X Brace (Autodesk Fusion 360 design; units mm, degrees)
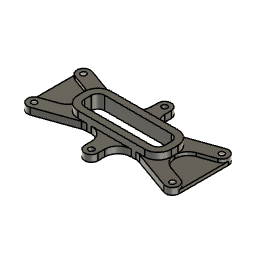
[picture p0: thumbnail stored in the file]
sketch "Sketch1" plane through (0, 0, 0) normal (0, 0, 1) x axis (1, 0, 0)
  line L1 (-44.45, -15.875) -> (44.45, -15.875)
  line L2 (-44.45, 15.875) -> (-44.45, -15.875)
  line L3 (44.45, 15.875) -> (-44.45, 15.875)
  line L4 (44.45, -15.875) -> (44.45, 15.875)
  line L5 (-44.45, 15.875) -> (44.45, -15.875)
  line L6 (44.45, 15.875) -> (-44.45, -15.875)
  line L7 (-63.6449, 29.4732) -> (67.9164, -17.513)
  line L8 (63.6449, -29.4732) -> (-67.9164, 17.513)
  line L9 (-65.7807, 23.4931) -> (65.7807, -23.4931)
  line L10 (67.9164, 17.513) -> (-63.6449, -29.4732)
  line L11 (-67.9164, -17.513) -> (63.6449, 29.4732)
  line L12 (65.7807, 23.4931) -> (-65.7807, -23.4931)
  line L13 (-72.1307, -23.4931) -> (-72.1307, 23.4931)
  line L14 (72.1307, -23.4931) -> (72.1307, 23.4931)
  arc A1 centre (-65.7807, 23.4931) radius 6.35 clockwise from (-67.9164, 17.513) to (-63.6449, 29.4732)
  arc A2 centre (65.7807, -23.4931) radius 6.35 clockwise from (67.9164, -17.513) to (63.6449, -29.4732)
  arc A3 centre (65.7807, 23.4931) radius 6.35 clockwise from (63.6449, 29.4732) to (67.9164, 17.513)
  arc A4 centre (-65.7807, -23.4931) radius 6.35 clockwise from (-63.6449, -29.4732) to (-67.9164, -17.513)
  point P6 (0, 0)
  point P1 (0, 0)
  point P13 (0, 0)
  point P20 (0, 0)
  point P21 (-72.1307, 23.4931)
  point P22 (-72.1307, -23.4931)
  point P23 (72.1307, 23.4931)
  point P24 (72.1307, -23.4931)
  point P4 (-44.45, 15.875)
  point P5 (44.45, 15.875)
  point P3 (-44.45, -15.875)
  point P11 (65.7807, -23.4931)
  point P12 (-65.7807, 23.4931)
  perpendicular L1 L2
  parallel L1 L3
  parallel L2 L4
  horizontal L1
  coincident L5 P6
  coincident L6 P6
  coincident P1 P6
  tangent L7 A1
  tangent A1 L8
  parallel L7 L8
  tangent L8 A2
  tangent L7 A2
  parallel L5 L9
  coincident L5 P13
  midpoint L9 P13
  coincident P1 P13
  tangent L10 A3
  tangent A3 L11
  parallel L10 L11
  tangent L11 A4
  tangent L10 A4
  parallel L6 L12
  coincident P13 P20
  midpoint L12 P20
  equal A2 A3
  equal L9 L12
  coincident A1 P21
  coincident A4 P22
  tangent A4 L13
  vertical L13
  coincident A3 P23
  coincident A2 P24
  tangent A2 L14
  vertical L14
  dimension "d1" distance P4 P5 = 88.9
  dimension "d2" distance P3 P4 = 31.75
  dimension "d3" radius A2 = 6.35
  dimension "d4" distance P11 P12 = 139.7
extrude "Extrude1" new body sketch "Sketch1" profile of L1 L2 L3 L4 L7 A1 L8 A2 L10 A3 L11 A4 along normal blind 6.35
extrude "Extrude2" add sketch "Sketch1" profile of L1 L2 L3 L4 L7 L8 L10 L11 along normal blind 12.7
fillet "Fillet1" radius 12.7
fillet "Fillet2" radius 12.7
sketch "Sketch2" plane through (0, 0, 12.7) normal (0, 0, 1) x axis (-1, 0, 0)
  line L1 (-31.75, 15.875) -> (31.75, 15.875)
  line L2 (-44.45, -3.175) -> (-44.45, 3.175)
  line L3 (31.75, -15.875) -> (-31.75, -15.875)
  line L4 (44.45, 3.175) -> (44.45, -3.175)
  line L5 (38.1, 3.175) -> (38.1, -3.175)
  line L6 (-31.75, 9.525) -> (31.75, 9.525)
  line L7 (-38.1, -3.175) -> (-38.1, 3.175)
  line L8 (31.75, -9.525) -> (-31.75, -9.525)
  arc A1 centre (31.75, 3.175) radius 12.7 clockwise from (31.75, 15.875) to (44.45, 3.175)
  arc A2 centre (-31.75, 3.175) radius 12.7 clockwise from (-44.45, 3.175) to (-31.75, 15.875)
  arc A3 centre (-31.75, -3.175) radius 12.7 clockwise from (-31.75, -15.875) to (-44.45, -3.175)
  arc A4 centre (31.75, -3.175) radius 12.7 clockwise from (44.45, -3.175) to (31.75, -15.875)
  arc A5 centre (31.75, 3.175) radius 6.35 clockwise from (31.75, 9.525) to (38.1, 3.175)
  arc A6 centre (-31.75, 3.175) radius 6.35 clockwise from (-38.1, 3.175) to (-31.75, 9.525)
  arc A7 centre (-31.75, -3.175) radius 6.35 clockwise from (-31.75, -9.525) to (-38.1, -3.175)
  arc A8 centre (31.75, -3.175) radius 6.35 clockwise from (38.1, -3.175) to (31.75, -9.525)
  dimension "d11" distance L4 = -6.35
extrude "Extrude3" cut sketch "Sketch2" profile of L5 A7 A5 L6 A6 L7 A8 L8 no distance stored
sketch "Sketch3" plane through (0, 0, 0) normal (0, 0, -1) x axis (1, 0, 0)
  line L1 (38.1, -3.175) -> (38.1, 3.175)
  line L2 (-31.75, -9.525) -> (31.75, -9.525)
  line L3 (-38.1, 3.175) -> (-38.1, -3.175)
  line L4 (31.75, 9.525) -> (-31.75, 9.525)
  line L5 (-44.45, -0.1822) -> (-44.45, 0.1822)
  line L6 (-67.9164, -17.513) -> (-52.8785, -12.1424)
  line L7 (-27.6418, -16.6149) -> (-63.6449, -29.4732)
  line L8 (23.3703, -15.875) -> (-23.3703, -15.875)
  line L9 (63.6449, -29.4732) -> (27.6418, -16.6149)
  line L10 (52.8785, -12.1424) -> (67.9164, -17.513)
  line L11 (44.45, 0.1822) -> (44.45, -0.1822)
  line L12 (67.9164, 17.513) -> (52.8785, 12.1424)
  line L13 (27.6418, 16.6149) -> (63.6449, 29.4732)
  line L14 (-23.3703, 15.875) -> (23.3703, 15.875)
  line L15 (-63.6449, 29.4732) -> (-27.6418, 16.6149)
  line L16 (-52.8785, 12.1424) -> (-67.9164, 17.513)
  arc A1 centre (31.75, -3.175) radius 6.35 clockwise from (38.1, -3.175) to (31.75, -9.525)
  arc A2 centre (-31.75, -3.175) radius 6.35 clockwise from (-31.75, -9.525) to (-38.1, -3.175)
  arc A3 centre (-31.75, 3.175) radius 6.35 clockwise from (-38.1, 3.175) to (-31.75, 9.525)
  arc A4 centre (31.75, 3.175) radius 6.35 clockwise from (31.75, 9.525) to (38.1, 3.175)
  arc A5 centre (-57.15, 0.1822) radius 12.7 clockwise from (-52.8785, 12.1424) to (-44.45, 0.1822)
  arc A6 centre (-57.15, -0.1822) radius 12.7 clockwise from (-44.45, -0.1822) to (-52.8785, -12.1424)
  arc A7 centre (-65.7807, -23.4931) radius 6.35 clockwise from (-63.6449, -29.4732) to (-67.9164, -17.513)
  arc A8 centre (-23.3703, -28.575) radius 12.7 clockwise from (-27.6418, -16.6149) to (-23.3703, -15.875)
  arc A9 centre (23.3703, -28.575) radius 12.7 clockwise from (23.3703, -15.875) to (27.6418, -16.6149)
  arc A10 centre (65.7807, -23.4931) radius 6.35 clockwise from (67.9164, -17.513) to (63.6449, -29.4732)
  arc A11 centre (57.15, -0.1822) radius 12.7 clockwise from (52.8785, -12.1424) to (44.45, -0.1822)
  arc A12 centre (57.15, 0.1822) radius 12.7 clockwise from (44.45, 0.1822) to (52.8785, 12.1424)
  arc A13 centre (65.7807, 23.4931) radius 6.35 clockwise from (63.6449, 29.4732) to (67.9164, 17.513)
  arc A14 centre (23.3703, 28.575) radius 12.7 clockwise from (27.6418, 16.6149) to (23.3703, 15.875)
  arc A15 centre (-23.3703, 28.575) radius 12.7 clockwise from (-23.3703, 15.875) to (-27.6418, 16.6149)
  arc A16 centre (-65.7807, 23.4931) radius 6.35 clockwise from (-67.9164, 17.513) to (-63.6449, 29.4732)
  point P52 (-65.7807, 23.4931)
  point P53 (-65.7807, 23.4931)
  point P23 (-65.7807, -23.4931)
  point P54 (-65.7807, -23.4931)
  point P42 (65.7807, 23.4931)
  point P55 (65.7807, 23.4931)
  point P33 (65.7807, -23.4931)
  point P56 (65.7807, -23.4931)
  coincident P52 P53
  coincident P23 P54
  coincident P42 P55
  coincident P33 P56
hole "Hole1" HoleDepth 9.525 HoleDiameter 5.1054 TipAngle 118
sketch "Sketch4" plane through (0, 0, 0) normal (0, 0, -1) x axis (1, 0, 0)
  line L1 (38.1, -3.175) -> (38.1, 3.175)
  line L2 (-31.75, -9.525) -> (31.75, -9.525)
  line L3 (-38.1, 3.175) -> (-38.1, -3.175)
  line L4 (31.75, 9.525) -> (-31.75, 9.525)
  line L5 (-44.45, -0.1822) -> (-44.45, 0.1822)
  line L6 (-67.9164, -17.513) -> (-52.8785, -12.1424)
  line L7 (-27.6418, -16.6149) -> (-63.6449, -29.4732)
  line L8 (23.3703, -15.875) -> (-23.3703, -15.875)
  line L9 (63.6449, -29.4732) -> (27.6418, -16.6149)
  line L10 (52.8785, -12.1424) -> (67.9164, -17.513)
  line L11 (44.45, 0.1822) -> (44.45, -0.1822)
  line L12 (67.9164, 17.513) -> (52.8785, 12.1424)
  line L13 (27.6418, 16.6149) -> (63.6449, 29.4732)
  line L14 (-23.3703, 15.875) -> (23.3703, 15.875)
  line L15 (-63.6449, 29.4732) -> (-27.6418, 16.6149)
  line L16 (-52.8785, 12.1424) -> (-67.9164, 17.513)
  line L17 (-56.126, 26.7878) -> (-60.3975, 14.8277)
  line L18 (6.35, 15.875) -> (-6.35, 15.875)
  line L19 (6.35, 34.925) -> (6.35, 15.875)
  line L20 (-6.35, 34.925) -> (6.35, 34.925)
  line L21 (-6.35, 15.875) -> (-6.35, 34.925)
  line L22 (6.35, -15.875) -> (-6.35, -15.875)
  line L23 (6.35, -34.925) -> (6.35, -15.875)
  line L24 (-6.35, -34.925) -> (6.35, -34.925)
  line L25 (-6.35, -15.875) -> (-6.35, -34.925)
  line L26 (0, -15.875) -> (0, 15.875)
  circle C1 centre (65.7807, 23.4931) radius 2.5578
  circle C2 centre (-65.7807, 23.4931) radius 2.5578
  circle C3 centre (-65.7807, -23.4931) radius 2.5578
  circle C4 centre (65.7807, -23.4931) radius 2.5578
  arc A1 centre (31.75, -3.175) radius 6.35 clockwise from (38.1, -3.175) to (31.75, -9.525)
  arc A2 centre (-31.75, -3.175) radius 6.35 clockwise from (-31.75, -9.525) to (-38.1, -3.175)
  arc A3 centre (-31.75, 3.175) radius 6.35 clockwise from (-38.1, 3.175) to (-31.75, 9.525)
  arc A4 centre (31.75, 3.175) radius 6.35 clockwise from (31.75, 9.525) to (38.1, 3.175)
  arc A5 centre (-57.15, 0.1822) radius 12.7 clockwise from (-52.8785, 12.1424) to (-44.45, 0.1822)
  arc A6 centre (-57.15, -0.1822) radius 12.7 clockwise from (-44.45, -0.1822) to (-52.8785, -12.1424)
  arc A7 centre (-65.7807, -23.4931) radius 6.35 clockwise from (-63.6449, -29.4732) to (-67.9164, -17.513)
  arc A8 centre (-23.3703, -28.575) radius 12.7 clockwise from (-27.6418, -16.6149) to (-23.3703, -15.875)
  arc A9 centre (23.3703, -28.575) radius 12.7 clockwise from (23.3703, -15.875) to (27.6418, -16.6149)
  arc A10 centre (65.7807, -23.4931) radius 6.35 clockwise from (67.9164, -17.513) to (63.6449, -29.4732)
  arc A11 centre (57.15, -0.1822) radius 12.7 clockwise from (52.8785, -12.1424) to (44.45, -0.1822)
  arc A12 centre (57.15, 0.1822) radius 12.7 clockwise from (44.45, 0.1822) to (52.8785, 12.1424)
  arc A13 centre (65.7807, 23.4931) radius 6.35 clockwise from (63.6449, 29.4732) to (67.9164, 17.513)
  arc A14 centre (23.3703, 28.575) radius 12.7 clockwise from (27.6418, 16.6149) to (23.3703, 15.875)
  arc A15 centre (-23.3703, 28.575) radius 12.7 clockwise from (-23.3703, 15.875) to (-27.6418, 16.6149)
  arc A16 centre (-65.7807, 23.4931) radius 6.35 clockwise from (-67.9164, 17.513) to (-63.6449, 29.4732)
  circle C5 centre (0, 34.925) radius 6.35
  circle C6 centre (0, -34.925) radius 6.35
  circle C7 centre (0, -34.925) radius 2.5578
  circle C8 centre (0, 34.925) radius 2.5578
  point P51 (-56.126, 26.7878)
  point P50 (-60.3975, 14.8277)
  point P52 (-6.35, 15.875)
  point P56 (-6.35, -15.875)
  point P60 (0, 15.875)
  point P61 (0, -15.875)
  point P1 (0, 0)
  point P62 (0, 34.925)
  point P54 (6.35, 34.925)
  point P63 (0, -34.925)
  point P58 (6.35, -34.925)
  point P55 (-6.35, 34.925)
  coincident L15 P51
  perpendicular L15 L17
  midpoint L16 P50
  horizontal L18
  vertical L19
  horizontal L20
  vertical L21
  coincident L14 P52
  horizontal L22
  vertical L23
  horizontal L24
  vertical L25
  coincident L8 P56
  equal L17 L20
  equal L17 L24
  midpoint L18 P60
  midpoint L22 P61
  vertical L26
  midpoint P1 L26
  equal L19 L23
  midpoint L20 P62
  coincident P54 C5
  midpoint L24 P63
  coincident P58 C6
  concentric C6 C7
  concentric C5 C8
  equal C2 C8
  equal C7 C8
  dimension "d16" distance P52 P55 = 19.05
extrude "Extrude4" add sketch "Sketch4" profile of L8 L14 L18 L19 L20 L21 L22 L23 L24 L25 C5 C6 C7 C8 to an object
fillet "Fillet3" radius 12.7
extrude "Extrude5" add sketch "Sketch1" profile of L2 L4 L7 A1 L8 A2 L10 A3 L11 A4 L13 L14 along normal blind 3.175
sketch "Sketch5" plane through (0, 0, 0) normal (0, 0, -1) x axis (1, 0, 0)
  line L1 (38.1, -3.175) -> (38.1, 3.175)
  line L2 (-31.75, -9.525) -> (31.75, -9.525)
  line L3 (-38.1, 3.175) -> (-38.1, -3.175)
  line L4 (31.75, 9.525) -> (-31.75, 9.525)
  line L5 (72.1307, 23.4931) -> (72.1307, -23.4931)
  line L6 (27.6418, 16.6149) -> (63.6449, 29.4732)
  line L7 (19.05, 15.875) -> (23.3703, 15.875)
  line L8 (6.35, 34.925) -> (6.35, 28.575)
  line L9 (-6.35, 28.575) -> (-6.35, 34.925)
  line L10 (-23.3703, 15.875) -> (-19.05, 15.875)
  line L11 (-63.6449, 29.4732) -> (-27.6418, 16.6149)
  line L12 (-72.1307, -23.4931) -> (-72.1307, 23.4931)
  line L13 (-27.6418, -16.6149) -> (-63.6449, -29.4732)
  line L14 (-19.05, -15.875) -> (-23.3703, -15.875)
  line L15 (-6.35, -34.925) -> (-6.35, -28.575)
  line L16 (6.35, -28.575) -> (6.35, -34.925)
  line L17 (23.3703, -15.875) -> (19.05, -15.875)
  line L18 (63.6449, -29.4732) -> (27.6418, -16.6149)
  line L19 (-52.8785, -12.1424) -> (-67.9164, -17.513)
  line L20 (-44.45, -3.175) -> (-44.45, -0.1822)
  line L21 (-23.3703, -15.875) -> (-31.75, -15.875)
  line L22 (-63.6449, -29.4732) -> (-27.6418, -16.6149)
  line L23 (-31.75, 15.875) -> (-23.3703, 15.875)
  line L24 (-44.45, 0.1822) -> (-44.45, 3.175)
  line L25 (-67.9164, 17.513) -> (-52.8785, 12.1424)
  line L26 (-27.6418, 16.6149) -> (-63.6449, 29.4732)
  line L27 (67.9164, -17.513) -> (52.8785, -12.1424)
  line L28 (27.6418, -16.6149) -> (63.6449, -29.4732)
  line L29 (31.75, -15.875) -> (23.3703, -15.875)
  line L30 (44.45, -0.1822) -> (44.45, -3.175)
  line L31 (23.3703, 15.875) -> (31.75, 15.875)
  line L32 (63.6449, 29.4732) -> (27.6418, 16.6149)
  line L33 (52.8785, 12.1424) -> (67.9164, 17.513)
  line L34 (44.45, 3.175) -> (44.45, 0.1822)
  line L35 (-30.7232, -9.4414) -> (-65.7807, -23.4931)
  line L36 (-43.3804, -17.9352) -> (-57.5264, -23.6052)
  line L37 (-59.8889, -17.711) -> (-45.7429, -12.0411)
  line L38 (-44.5617, -14.9881) -> (-58.7077, -20.6581)
  line L39 (0, 34.925) -> (0, 0)
  line L40 (59.8889, -17.711) -> (45.7429, -12.0411)
  line L41 (43.3804, -17.9352) -> (57.5264, -23.6052)
  line L42 (57.15, 0.1822) -> (0, 0)
  line L43 (-60.0007, 17.3287) -> (-45.8188, 11.7491)
  line L44 (-43.4939, 17.6582) -> (-57.6758, 23.2378)
  line L45 (59.7747, 18.0926) -> (45.6652, 12.3325)
  line L46 (43.2652, 18.2115) -> (57.3747, 23.9716)
  circle C1 centre (0, -34.925) radius 2.5578
  circle C2 centre (0, 34.925) radius 2.5578
  circle C3 centre (65.7807, 23.4931) radius 2.5578
  circle C4 centre (-65.7807, 23.4931) radius 2.5578
  circle C5 centre (-65.7807, -23.4931) radius 2.5578
  circle C6 centre (65.7807, -23.4931) radius 2.5578
  arc A1 centre (31.75, -3.175) radius 6.35 clockwise from (38.1, -3.175) to (31.75, -9.525)
  arc A2 centre (-31.75, -3.175) radius 6.35 clockwise from (-31.75, -9.525) to (-38.1, -3.175)
  arc A3 centre (-31.75, 3.175) radius 6.35 clockwise from (-38.1, 3.175) to (-31.75, 9.525)
  arc A4 centre (31.75, 3.175) radius 6.35 clockwise from (31.75, 9.525) to (38.1, 3.175)
  arc A5 centre (65.7807, 23.4931) radius 6.35 clockwise from (63.6449, 29.4732) to (72.1307, 23.4931)
  arc A6 centre (23.3703, 28.575) radius 12.7 clockwise from (27.6418, 16.6149) to (23.3703, 15.875)
  arc A7 centre (19.05, 28.575) radius 12.7 clockwise from (19.05, 15.875) to (6.35, 28.575)
  arc A8 centre (0, 34.925) radius 6.35 clockwise from (-6.35, 34.925) to (6.35, 34.925)
  arc A9 centre (-19.05, 28.575) radius 12.7 clockwise from (-6.35, 28.575) to (-19.05, 15.875)
  arc A10 centre (-23.3703, 28.575) radius 12.7 clockwise from (-23.3703, 15.875) to (-27.6418, 16.6149)
  arc A11 centre (-65.7807, 23.4931) radius 6.35 clockwise from (-72.1307, 23.4931) to (-63.6449, 29.4732)
  arc A12 centre (-65.7807, -23.4931) radius 6.35 clockwise from (-63.6449, -29.4732) to (-72.1307, -23.4931)
  arc A13 centre (-23.3703, -28.575) radius 12.7 clockwise from (-27.6418, -16.6149) to (-23.3703, -15.875)
  arc A14 centre (-19.05, -28.575) radius 12.7 clockwise from (-19.05, -15.875) to (-6.35, -28.575)
  arc A15 centre (0, -34.925) radius 6.35 clockwise from (6.35, -34.925) to (-6.35, -34.925)
  arc A16 centre (19.05, -28.575) radius 12.7 clockwise from (6.35, -28.575) to (19.05, -15.875)
  arc A17 centre (23.3703, -28.575) radius 12.7 clockwise from (23.3703, -15.875) to (27.6418, -16.6149)
  arc A18 centre (65.7807, -23.4931) radius 6.35 clockwise from (72.1307, -23.4931) to (63.6449, -29.4732)
  circle C7 centre (-65.7807, -23.4931) radius 2.5578
  arc A19 centre (-57.15, -0.1822) radius 12.7 clockwise from (-44.45, -0.1822) to (-52.8785, -12.1424)
  arc A20 centre (-31.75, -3.175) radius 12.7 clockwise from (-31.75, -15.875) to (-44.45, -3.175)
  arc A21 centre (-23.3703, -28.575) radius 12.7 clockwise from (-27.6418, -16.6149) to (-23.3703, -15.875)
  arc A22 centre (-65.7807, -23.4931) radius 6.35 clockwise from (-63.6449, -29.4732) to (-67.9164, -17.513)
  circle C8 centre (-65.7807, 23.4931) radius 2.5578
  arc A23 centre (-31.75, 3.175) radius 12.7 clockwise from (-44.45, 3.175) to (-31.75, 15.875)
  arc A24 centre (-57.15, 0.1822) radius 12.7 clockwise from (-52.8785, 12.1424) to (-44.45, 0.1822)
  arc A25 centre (-65.7807, 23.4931) radius 6.35 clockwise from (-67.9164, 17.513) to (-63.6449, 29.4732)
  arc A26 centre (-23.3703, 28.575) radius 12.7 clockwise from (-23.3703, 15.875) to (-27.6418, 16.6149)
  circle C9 centre (65.7807, -23.4931) radius 2.5578
  arc A27 centre (65.7807, -23.4931) radius 6.35 clockwise from (67.9164, -17.513) to (63.6449, -29.4732)
  arc A28 centre (23.3703, -28.575) radius 12.7 clockwise from (23.3703, -15.875) to (27.6418, -16.6149)
  arc A29 centre (31.75, -3.175) radius 12.7 clockwise from (44.45, -3.175) to (31.75, -15.875)
  arc A30 centre (57.15, -0.1822) radius 12.7 clockwise from (52.8785, -12.1424) to (44.45, -0.1822)
  circle C10 centre (65.7807, 23.4931) radius 2.5578
  arc A31 centre (23.3703, 28.575) radius 12.7 clockwise from (27.6418, 16.6149) to (23.3703, 15.875)
  arc A32 centre (65.7807, 23.4931) radius 6.35 clockwise from (63.6449, 29.4732) to (67.9164, 17.513)
  arc A33 centre (57.15, 0.1822) radius 12.7 clockwise from (44.45, 0.1822) to (52.8785, 12.1424)
  arc A34 centre (31.75, 3.175) radius 12.7 clockwise from (31.75, 15.875) to (44.45, 3.175)
  arc A35 centre (-44.5617, -14.9881) radius 3.175 clockwise from (-45.7429, -12.0411) to (-43.3804, -17.9352)
  arc A36 centre (-58.7077, -20.6581) radius 3.175 clockwise from (-57.5264, -23.6052) to (-59.8889, -17.711)
  arc A37 centre (58.7077, -20.6581) radius 3.175 clockwise from (59.8889, -17.711) to (57.5264, -23.6052)
  arc A38 centre (44.5617, -14.9881) radius 3.175 clockwise from (43.3804, -17.9352) to (45.7429, -12.0411)
  arc A39 centre (-58.8382, 20.2833) radius 3.175 clockwise from (-60.0007, 17.3287) to (-57.6758, 23.2378)
  arc A40 centre (-44.6564, 14.7036) radius 3.175 clockwise from (-43.4939, 17.6582) to (-45.8188, 11.7491)
  arc A41 centre (44.4652, 15.272) radius 3.175 clockwise from (45.6652, 12.3325) to (43.2652, 18.2115)
  arc A42 centre (58.5747, 21.0321) radius 3.175 clockwise from (57.3747, 23.9716) to (59.7747, 18.0926)
  point P56 (-65.7807, -23.4931)
  point P104 (-65.7807, -23.4931)
  point P105 (-30.7232, -9.4414)
  point P111 (-44.5617, -14.9881)
  point P1 (0, 0)
  point P112 (0, 0)
  point P3 (0, 34.925)
  point P113 (0, 34.925)
  point P106 (-57.5264, -23.6052)
  point P117 (57.5264, -23.6052)
  point P107 (-43.3804, -17.9352)
  point P118 (43.3804, -17.9352)
  point P108 (-45.7429, -12.0411)
  point P114 (45.7429, -12.0411)
  point P109 (-59.8889, -17.711)
  point P115 (59.8889, -17.711)
  point P101 (57.15, 0.1822)
  point P120 (57.15, 0.1822)
  point P124 (-57.6758, 23.2378)
  point P125 (-43.4939, 17.6582)
  point P121 (-45.8188, 11.7491)
  point P122 (-60.0007, 17.3287)
  point P128 (45.6652, 12.3325)
  point P130 (59.7747, 18.0926)
  point P131 (57.3747, 23.9716)
  point P129 (43.2652, 18.2115)
  point P110 (-58.7077, -20.6581)
  coincident P56 P104
  coincident A2 P105
  tangent L36 A35
  tangent A35 L37
  parallel L36 L37
  tangent L37 A36
  tangent L36 A36
  coincident L35 P111
  parallel L35 L38
  coincident P1 P112
  coincident P3 P113
  symmetric P106 L39 P117
  symmetric P107 L39 P118
  symmetric P108 L39 P114
  symmetric P109 L39 P115
  symmetric A35 L39 A38
  symmetric A36 L39 A37
  coincident P101 P120
  symmetric P106 L42 P124
  symmetric P107 L42 P125
  symmetric P108 L42 P121
  symmetric P109 L42 P122
  symmetric A35 L42 A40
  symmetric A36 L42 A39
  symmetric P114 L42 P128
  symmetric P115 L42 P130
  symmetric P117 L42 P131
  symmetric A37 L42 A42
  symmetric P118 L42 P129
  symmetric A38 L42 A41
  dimension "d27" diameter A35 = 6.35
  dimension "d28" distance P110 P111 = 15.24
  dimension "d29" angle L14 L35 = 21.842
  dimension "d30" distance P56 P110 = 7.62
extrude "Extrude6" cut sketch "Sketch5" profile of L35 L36 A35 L37 A36 L40 A37 L41 A38 L43 A39 L44 A40 A41 L45 L46 A42 against normal blind 3.175
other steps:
thread "Thread1"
